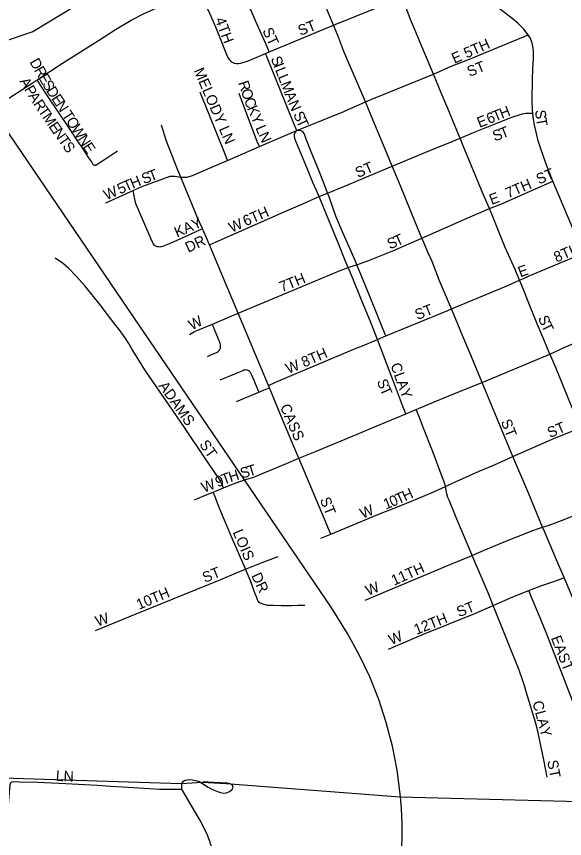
# Model space of a CAD drawing. Extents: x 0 to 34, y 0 to 22.
# Drawn here: x 30.158 to 30.651, y 14.628 to 15.366 of the extents above; entities that cross this region are included whole.
import ezdxf

# ---------------------------------------------------------------- set-up
doc = ezdxf.new("R2010")
doc.units = 0
for name, color, linetype in [('GM_X_City_Street', 7, 'Continuous'), ('GM_X_City_Street_Text', 7, 'Continuous'), ('GM_X_Corporation', 7, 'Continuous'), ('GM_X_Minor_River', 7, 'Continuous'), ('GM_X_State_Route', 7, 'Continuous'), ('GM_X_Township_Subdivision', 7, 'Continuous'), ('GM_X_Township_Subdivision_Text', 7, 'Continuous')]:
    doc.layers.add(name, color=color, linetype=linetype)

msp = doc.modelspace()

# ---------------------------------------------------------------- linework, layer by layer
at = {"layer": 'GM_X_City_Street'}
for points in [[(30.44327, 15.35778), (30.44035, 15.36499), (30.43212, 15.38492), (30.41886, 15.41649), (30.41429, 15.42742)], [(30.38556, 15.33389), (30.38354, 15.33843), (30.37364, 15.36119), (30.35762, 15.39828), (30.35533, 15.40356)], [(30.32272, 15.39), (30.32449, 15.38561), (30.32564, 15.38274), (30.32807, 15.37706), (30.33177, 15.36859), (30.33729, 15.35644), (30.34708, 15.33163), (30.34844, 15.32882), (30.34951, 15.32715), (30.35046, 15.32608), (30.35118, 15.32532), (30.35217, 15.32468), (30.35347, 15.32402), (30.35414, 15.32378), (30.35494, 15.32363), (30.35621, 15.3235), (30.35783, 15.32355), (30.35979, 15.32379), (30.36296, 15.32452), (30.36594, 15.32568), (30.38214, 15.33238)], [(30.61816, 15.34911), (30.61424, 15.35417), (30.61213, 15.35645), (30.60908, 15.35949), (30.60332, 15.36421), (30.59357, 15.37159), (30.5698, 15.39064)], [(30.44327, 15.35778), (30.50042, 15.38133), (30.50431, 15.38294)], [(30.53298, 15.31403), (30.52824, 15.32523), (30.52254, 15.33874), (30.52042, 15.3437), (30.51589, 15.3547), (30.51247, 15.36302), (30.5102, 15.36868), (30.50905, 15.37147), (30.50559, 15.3799), (30.50431, 15.38294)], [(30.17702, 15.30874), (30.19984, 15.32373), (30.23212, 15.34424), (30.24739, 15.35406), (30.26162, 15.36231), (30.27335, 15.36832), (30.29192, 15.37678)], [(30.38556, 15.33389), (30.4006, 15.34017), (30.44327, 15.35778)], [(30.47211, 15.28905), (30.46484, 15.30582), (30.45611, 15.32576), (30.45255, 15.33435), (30.447, 15.34855), (30.44327, 15.35778)], [(30.53298, 15.31403), (30.54819, 15.32065), (30.5639, 15.32686), (30.61395, 15.34738), (30.61816, 15.34911)], [(30.62214, 15.27888), (30.62186, 15.28172), (30.6216, 15.2909), (30.62194, 15.30942), (30.62228, 15.31867), (30.62279, 15.32791), (30.62296, 15.33419), (30.6227, 15.33736), (30.62208, 15.3405), (30.62108, 15.34354), (30.61974, 15.34643), (30.61816, 15.34911)], [(30.38214, 15.33238), (30.38556, 15.33389)], [(30.41019, 15.26328), (30.40817, 15.26814), (30.40136, 15.28521), (30.38362, 15.32883), (30.38214, 15.33238)], [(30.13629, 15.28267), (30.17253, 15.30579), (30.17702, 15.30874)], [(30.2494, 15.24479), (30.23857, 15.23768), (30.23007, 15.23214), (30.22965, 15.23192), (30.22933, 15.23187), (30.22898, 15.23186), (30.2286, 15.23197), (30.22824, 15.23219), (30.22767, 15.23266), (30.22746, 15.23297), (30.22581, 15.23543), (30.22353, 15.23877), (30.21756, 15.24817), (30.21433, 15.25286), (30.20568, 15.26591), (30.18626, 15.29435), (30.17952, 15.30486), (30.17702, 15.30874)], [(30.47211, 15.28905), (30.47759, 15.29146), (30.53298, 15.31403)], [(30.55689, 15.25657), (30.55641, 15.25771), (30.54583, 15.28314), (30.54001, 15.29701), (30.53298, 15.31403)], [(30.34806, 15.2365), (30.3459, 15.24198), (30.32358, 15.29783)], [(30.37664, 15.24885), (30.37483, 15.25357), (30.36266, 15.28528), (30.35855, 15.29668)], [(30.41019, 15.26328), (30.45242, 15.28035), (30.47211, 15.28905)], [(30.49591, 15.23135), (30.49102, 15.24296), (30.48038, 15.26877), (30.47211, 15.28905)], [(30.55689, 15.25657), (30.56902, 15.26143), (30.59304, 15.27098), (30.6043, 15.2755), (30.61006, 15.27751), (30.61305, 15.2783), (30.61595, 15.27877), (30.61881, 15.27901), (30.62214, 15.27888)], [(30.64034, 15.21782), (30.63697, 15.22615), (30.63384, 15.23414), (30.63143, 15.24092), (30.62962, 15.24599), (30.6272, 15.2542), (30.62566, 15.26068), (30.62344, 15.2696), (30.62245, 15.27563), (30.62214, 15.27888)], [(30.30615, 15.22134), (30.30347, 15.22774), (30.29335, 15.25378), (30.28871, 15.26823)], [(30.37664, 15.24885), (30.41019, 15.26328)], [(30.43023, 15.20408), (30.42461, 15.21663), (30.41977, 15.2285), (30.40939, 15.25364), (30.40863, 15.25604), (30.40825, 15.25845), (30.40832, 15.25996), (30.40882, 15.26148), (30.41019, 15.26328)], [(30.43794, 15.20724), (30.43599, 15.21218), (30.43025, 15.22682), (30.42332, 15.24413), (30.41884, 15.25549), (30.41781, 15.25821), (30.4168, 15.26059), (30.41597, 15.26174), (30.41471, 15.26275), (30.41331, 15.26325), (30.41019, 15.26328)], [(30.49591, 15.23135), (30.52966, 15.24528), (30.5497, 15.25359), (30.55689, 15.25657)], [(30.58334, 15.19328), (30.57781, 15.20616), (30.55983, 15.24956), (30.55689, 15.25657)], [(30.34806, 15.2365), (30.37664, 15.24885)], [(30.30615, 15.22134), (30.31185, 15.22134), (30.31656, 15.22281), (30.33443, 15.23061), (30.34806, 15.2365)], [(30.43794, 15.20724), (30.45244, 15.21317), (30.48672, 15.22756), (30.49591, 15.23135)], [(30.52257, 15.1668), (30.51837, 15.17697), (30.51361, 15.18842), (30.50665, 15.2057), (30.50189, 15.21719), (30.49591, 15.23135)], [(30.26333, 15.20939), (30.26845, 15.21189), (30.27435, 15.21439), (30.28834, 15.21939), (30.29651, 15.22229), (30.30072, 15.22238), (30.30615, 15.22134)], [(30.32569, 15.17513), (30.32551, 15.17552), (30.32303, 15.18098), (30.32064, 15.18647), (30.31613, 15.19744), (30.31167, 15.20816), (30.30615, 15.22134)], [(30.58334, 15.19328), (30.59348, 15.19731), (30.64034, 15.21782)], [(30.66776, 15.15339), (30.66601, 15.15747), (30.65677, 15.17901), (30.64034, 15.21782)], [(30.23863, 15.19836), (30.26333, 15.20939)], [(30.32569, 15.17513), (30.32359, 15.17416), (30.31115, 15.16845), (30.29983, 15.1633), (30.29405, 15.16097), (30.29116, 15.15976), (30.28954, 15.15914), (30.28831, 15.15885), (30.28738, 15.15876), (30.28642, 15.15882), (30.28528, 15.15895), (30.28429, 15.15927), (30.28347, 15.15955), (30.28279, 15.16), (30.28229, 15.16044), (30.28136, 15.16185), (30.28073, 15.16299), (30.27942, 15.16584), (30.26712, 15.19422), (30.26594, 15.19704), (30.26527, 15.20002), (30.26448, 15.2031), (30.26333, 15.20939)], [(30.43023, 15.20408), (30.43794, 15.20724)], [(30.46431, 15.14293), (30.46272, 15.14681), (30.45009, 15.17498), (30.44544, 15.1864), (30.43928, 15.20386), (30.43794, 15.20724)], [(30.33188, 15.16081), (30.33726, 15.16318), (30.399, 15.19044), (30.41579, 15.19765), (30.42896, 15.20352), (30.43023, 15.20408)], [(30.45642, 15.1404), (30.45384, 15.14659), (30.44816, 15.16101), (30.43282, 15.19827), (30.43023, 15.20408)], [(30.52257, 15.1668), (30.55848, 15.18246), (30.57077, 15.18799), (30.57574, 15.19003), (30.57902, 15.19155), (30.58334, 15.19328)], [(30.61032, 15.12891), (30.60629, 15.13851), (30.59744, 15.15833), (30.58611, 15.18684), (30.58334, 15.19328)], [(30.33188, 15.16081), (30.32918, 15.16713), (30.32569, 15.17513)], [(30.35763, 15.09937), (30.35671, 15.10154), (30.33887, 15.14442), (30.33281, 15.15864), (30.33188, 15.16081)], [(30.46431, 15.14293), (30.46892, 15.14446), (30.47416, 15.14631), (30.49666, 15.15547), (30.52257, 15.1668)], [(30.54919, 15.10323), (30.53858, 15.12834), (30.53183, 15.14577), (30.52799, 15.15424), (30.52425, 15.16272), (30.52257, 15.1668)], [(30.61032, 15.12891), (30.61341, 15.13028), (30.61911, 15.1328), (30.66776, 15.15339)], [(30.34441, 14.94265), (30.34259, 14.94696), (30.34043, 14.95087), (30.32776, 14.96957), (30.30872, 14.99775), (30.29295, 15.02063), (30.28416, 15.03328), (30.27378, 15.04863), (30.26887, 15.05646), (30.26247, 15.06696), (30.25942, 15.07227), (30.25613, 15.07741), (30.25066, 15.08478), (30.2469, 15.08965), (30.23367, 15.10676), (30.22011, 15.12365), (30.21194, 15.13293), (30.20545, 15.13955), (30.20074, 15.14354), (30.19315, 15.14886)], [(30.35763, 15.09937), (30.39772, 15.11613), (30.44927, 15.13783), (30.45642, 15.1404)], [(30.45642, 15.1404), (30.46193, 15.14213), (30.46431, 15.14293)], [(30.48266, 15.0759), (30.47683, 15.09093), (30.46823, 15.11209), (30.46071, 15.13049), (30.45642, 15.1404)], [(30.49021, 15.07899), (30.48791, 15.0847), (30.48363, 15.09533), (30.47544, 15.11533), (30.47089, 15.12681), (30.46431, 15.14293)], [(30.54919, 15.10323), (30.60048, 15.1245), (30.61032, 15.12891)], [(30.63742, 15.06251), (30.63228, 15.07584), (30.62631, 15.08994), (30.61914, 15.10697), (30.6123, 15.1242), (30.61032, 15.12891)], [(30.49021, 15.07899), (30.54586, 15.10185), (30.54919, 15.10323)], [(30.57663, 15.03734), (30.56647, 15.06173), (30.55925, 15.07935), (30.54919, 15.10323)], [(30.33445, 15.08969), (30.35763, 15.09937)], [(30.38485, 15.03464), (30.35763, 15.09937)], [(30.31386, 15.08018), (30.31842, 15.08299), (30.33445, 15.08969)], [(30.33016, 15.06061), (30.33303, 15.06202), (30.33594, 15.06321), (30.33881, 15.06453), (30.33957, 15.065), (30.34044, 15.06582), (30.341, 15.06668), (30.34138, 15.06731), (30.34172, 15.06814), (30.34186, 15.06893), (30.3419, 15.0699), (30.34176, 15.07092), (30.34143, 15.07215), (30.34112, 15.07305), (30.34, 15.07604), (30.33639, 15.08491), (30.33445, 15.08969)], [(30.63742, 15.06251), (30.65037, 15.0686), (30.68858, 15.08499), (30.69477, 15.08749)], [(30.48266, 15.0759), (30.49021, 15.07899)], [(30.38485, 15.03464), (30.39063, 15.03708), (30.46372, 15.06792), (30.46934, 15.07025), (30.48266, 15.0759)], [(30.50817, 15.00905), (30.50536, 15.0165), (30.49899, 15.03337), (30.48266, 15.0759)], [(30.34158, 15.03974), (30.35601, 15.04572), (30.36169, 15.04808), (30.3628, 15.04853), (30.36362, 15.0487), (30.3645, 15.04874), (30.36545, 15.04863), (30.36642, 15.04827), (30.36696, 15.04801), (30.36744, 15.04762), (30.36785, 15.04715), (30.36828, 15.04658), (30.36927, 15.04482), (30.3718, 15.03918), (30.37297, 15.03635), (30.37625, 15.02846)], [(30.38577, 15.03246), (30.38552, 15.03306), (30.38485, 15.03464)], [(30.60437, 14.97069), (30.60282, 14.97432), (30.57663, 15.03734)], [(30.3561, 15.02001), (30.37625, 15.02846)], [(30.37625, 15.02846), (30.38253, 15.0311), (30.38577, 15.03246)], [(30.41221, 14.96916), (30.40763, 14.97988), (30.39603, 15.00757), (30.38577, 15.03246)], [(30.54377, 14.94398), (30.54319, 14.94604), (30.5426, 14.94821), (30.54099, 14.9525), (30.53203, 14.97581), (30.52415, 14.99616), (30.51985, 15.00716), (30.51757, 15.013)], [(30.60437, 14.97069), (30.64173, 14.98723), (30.65912, 14.99401), (30.66524, 14.9964)], [(30.44077, 14.9012), (30.43876, 14.90594), (30.43756, 14.90878), (30.41221, 14.96916)], [(30.54377, 14.94398), (30.5508, 14.94718), (30.5741, 14.9575), (30.58784, 14.96334), (30.60437, 14.97069)], [(30.6311, 14.90735), (30.61858, 14.93738), (30.60437, 14.97069)], [(30.34441, 14.94265), (30.35264, 14.94611), (30.36327, 14.94984)], [(30.3184, 14.93198), (30.32123, 14.9331), (30.32691, 14.93539), (30.33532, 14.93884)], [(30.33532, 14.93884), (30.34441, 14.94265)], [(30.36427, 14.86961), (30.36381, 14.87072), (30.3516, 14.89877), (30.34716, 14.90937), (30.34357, 14.91774), (30.33964, 14.92748), (30.33639, 14.93603), (30.33532, 14.93884)], [(30.52401, 14.9353), (30.53385, 14.93942), (30.54377, 14.94398)], [(30.56783, 14.88208), (30.56744, 14.88297), (30.55412, 14.91454), (30.54705, 14.9315), (30.54606, 14.93387), (30.54497, 14.93733), (30.54438, 14.9405), (30.54377, 14.94398)], [(30.44077, 14.9012), (30.48458, 14.91923), (30.49914, 14.9251), (30.5168, 14.93234), (30.52401, 14.9353)], [(30.6311, 14.90735), (30.636, 14.9089), (30.64168, 14.91111), (30.65028, 14.9144), (30.68274, 14.92753), (30.69145, 14.93139)], [(30.56783, 14.88208), (30.57232, 14.88393), (30.59644, 14.8942), (30.62228, 14.90447), (30.62734, 14.90625), (30.63005, 14.90701), (30.6311, 14.90735)], [(30.65042, 14.86209), (30.64511, 14.87441), (30.63294, 14.90298), (30.6311, 14.90735)], [(30.43197, 14.8974), (30.44077, 14.9012)], [(30.36427, 14.86961), (30.37917, 14.87559), (30.39359, 14.8811)], [(30.47165, 14.84195), (30.54855, 14.87415), (30.56783, 14.88208)], [(30.58668, 14.83717), (30.58216, 14.84842), (30.56783, 14.88208)], [(30.22955, 14.81474), (30.26607, 14.82954), (30.34195, 14.86049), (30.35621, 14.86638), (30.36427, 14.86961)], [(30.3765, 14.83991), (30.3757, 14.84088), (30.37498, 14.84227), (30.37397, 14.84492), (30.37304, 14.84763), (30.36866, 14.85928), (30.36427, 14.86961)], [(30.61857, 14.8506), (30.62169, 14.85188), (30.63044, 14.85513), (30.63935, 14.85796), (30.64764, 14.86105), (30.65042, 14.86209)], [(30.65834, 14.84366), (30.65042, 14.86209)], [(30.58668, 14.83717), (30.60442, 14.84482), (30.61857, 14.8506)], [(30.66168, 14.73817), (30.66142, 14.74073), (30.661, 14.74272), (30.66062, 14.74412), (30.6596, 14.74701), (30.63424, 14.81277), (30.62739, 14.82973), (30.62144, 14.84381), (30.61857, 14.8506)], [(30.41756, 14.83715), (30.41139, 14.83699), (30.40545, 14.83692), (30.39623, 14.83679), (30.38944, 14.83699), (30.3841, 14.83725), (30.38084, 14.83796), (30.37835, 14.83877), (30.37734, 14.83928), (30.3765, 14.83991)], [(30.49275, 14.79792), (30.52421, 14.81129), (30.57021, 14.83004), (30.58668, 14.83717)], [(30.63507, 14.68296), (30.6323, 14.69869), (30.62864, 14.7158), (30.62687, 14.7244), (30.6248, 14.73244), (30.61658, 14.75882), (30.615, 14.76416), (30.61301, 14.77048), (30.60998, 14.77912), (30.58668, 14.83717)]]:
    msp.add_lwpolyline(points, dxfattribs=at)
at = {"layer": 'GM_X_Corporation'}
msp.add_lwpolyline([(29.75791, 15.20851), (29.79058, 15.21093), (29.86115, 15.29432), (29.91553, 15.1943), (29.9416, 15.13863), (29.94194, 15.10088), (29.94871, 15.04567), (29.96989, 14.94591), (30.07764, 14.93075), (30.06917, 14.68585), (30.09828, 14.68409), (30.30666, 14.67751), (30.32534, 14.67859), (30.34695, 14.67725), (30.50269, 14.66532), (30.73315, 14.65946), (30.803, 14.661), (30.81667, 14.62861)], dxfattribs=at)
at = {"layer": 'GM_X_Minor_River'}
msp.add_lwpolyline([(30.26003, 15.68689), (30.2593, 15.66897), (30.26815, 15.6398), (30.27368, 15.59278), (30.26354, 15.48955), (30.26512, 15.474), (30.27124, 15.46378), (30.26863, 15.45315), (30.25321, 15.42691), (30.21176, 15.37513), (30.1732, 15.35183), (30.124, 15.3353), (30.06759, 15.3214), (30.02369, 15.30528), (29.99036, 15.30096), (29.94494, 15.28748), (29.91698, 15.26877), (29.86752, 15.22531), (29.84824, 15.21385), (29.81119, 15.19358), (29.77572, 15.16004)], dxfattribs=at)
at = {"layer": 'GM_X_State_Route'}
for points in [[(30.36327, 14.94984), (30.35876, 14.95655), (30.2641, 15.09534), (30.13629, 15.28267), (30.11506, 15.3138), (30.09374, 15.34496), (30.0929, 15.3462)], [(30.36327, 14.94984), (30.37059, 14.95202), (30.37317, 14.95293), (30.37648, 14.95426), (30.40118, 14.96455), (30.41221, 14.96916), (30.42703, 14.97536), (30.46441, 14.99085), (30.48165, 14.99794), (30.49885, 15.00514), (30.50817, 15.00905), (30.51757, 15.013), (30.53319, 15.01955), (30.5579, 15.02959), (30.57663, 15.03734), (30.62109, 15.05576), (30.63742, 15.06251)], [(30.63742, 15.06251), (30.64285, 15.04994), (30.6488, 15.03548), (30.65465, 15.02134), (30.65703, 15.01572), (30.65943, 15.01015), (30.66299, 15.00186), (30.66524, 14.9964), (30.68036, 14.95966), (30.68245, 14.95396), (30.68463, 14.94828), (30.68697, 14.94263), (30.69145, 14.93139)], [(30.50346, 14.66582), (30.50045, 14.68943), (30.49621, 14.71085), (30.49067, 14.73197), (30.48386, 14.75271), (30.47579, 14.77301), (30.4664, 14.79272), (30.45591, 14.81186), (30.44106, 14.83566), (30.36327, 14.94984)], [(30.41106, 14.2976), (30.44516, 14.37223), (30.45625, 14.3969), (30.46221, 14.4113), (30.46824, 14.42901), (30.47342, 14.44835), (30.47623, 14.45958), (30.47826, 14.46865), (30.48359, 14.49251), (30.49722, 14.55635), (30.50129, 14.58093), (30.50339, 14.59947), (30.50475, 14.62122), (30.50481, 14.62824), (30.50493, 14.63438), (30.50484, 14.64237), (30.50458, 14.64816), (30.50423, 14.65453), (30.50349, 14.66561), (30.50346, 14.66582)]]:
    msp.add_lwpolyline(points, dxfattribs=at)
at = {"layer": 'GM_X_Township_Subdivision'}
for points in [[(30.3069, 14.67216), (30.30708, 14.6761), (30.30746, 14.67781), (30.30861, 14.67948), (30.31, 14.68033), (30.31328, 14.68093), (30.31653, 14.68073), (30.31966, 14.68015), (30.32269, 14.67905), (30.32551, 14.67752), (30.33075, 14.67416), (30.3334, 14.67269), (30.33614, 14.67137), (30.33897, 14.67019), (30.34182, 14.66915), (30.34454, 14.66866), (30.34713, 14.66904), (30.34974, 14.67016), (30.35204, 14.67183), (30.35323, 14.67387), (30.35267, 14.67579), (30.35059, 14.67702), (30.34775, 14.67754), (30.34164, 14.67796), (30.33545, 14.67825), (30.32613, 14.67888)], [(30.14839, 14.62282), (30.14892, 14.62905), (30.15298, 14.67664), (30.15306, 14.67709), (30.15313, 14.67758), (30.15354, 14.67838), (30.15439, 14.67884), (30.15549, 14.67904), (30.16102, 14.67896), (30.17783, 14.6785), (30.20284, 14.67738), (30.23094, 14.67575), (30.24335, 14.67497), (30.25886, 14.67407), (30.2776, 14.67289), (30.28699, 14.67239), (30.29637, 14.6722), (30.3069, 14.67216)], [(30.34328, 14.57631), (30.3398, 14.59544), (30.33791, 14.60451), (30.3348, 14.6165), (30.33211, 14.62535), (30.32999, 14.63109), (30.32751, 14.63663), (30.32318, 14.64467), (30.31243, 14.66307), (30.3069, 14.67216)]]:
    msp.add_lwpolyline(points, dxfattribs=at)

# ---------------------------------------------------------------- texts
at = {"layer": 'GM_X_City_Street_Text'}
for s, rotation, p in [('4TH', 290.55505, (30.33672, 15.36294)), ('ST', 21.80392, (30.41355, 15.34814)), ('ST', 295.02966, (30.37916, 15.35307)), ('E 5TH', 23.80864, (30.55187, 15.32313)), ('S', 291.42594, (30.38671, 15.32796)), ('D', 299.57682, (30.16994, 15.32485)), ('I', 291.46546, (30.38914, 15.32175)), ('ST', 21.80141, (30.56544, 15.31134)), ('R', 299.61345, (30.17405, 15.3176)), ('MELODY LN', 293.38335, (30.31752, 15.31719)), ('L', 291.42594, (30.39067, 15.31788)), ('A', 300.9975, (30.16087, 15.30748)), ('E', 299.80675, (30.17777, 15.31104)), ('S', 301.30715, (30.18123, 15.30503)), ('R', 288.51176, (30.35757, 15.30621)), ('L', 291.43089, (30.3931, 15.31167)), ('M', 291.4429, (30.39554, 15.30547)), ('P', 301.29035, (30.16519, 15.30029)), ('D', 302.82743, (30.18484, 15.2991)), ('O', 288.48334, (30.35996, 15.2991)), ('A', 302.20933, (30.16874, 15.29445)), ('E', 303.75379, (30.18945, 15.29196)), ('A', 291.4728, (30.3992, 15.29615)), ('R', 303.10373, (30.17326, 15.28726)), ('T', 304.10148, (30.17746, 15.28083)), ('N', 303.05961, (30.19314, 15.28644)), ('C', 290.26259, (30.36271, 15.29089)), ('K', 293.01017, (30.36548, 15.2834)), ('N', 293.44813, (30.40239, 15.28807)), ('H', 21.83794, (30.59451, 15.2737)), ('M', 304.66343, (30.18126, 15.27523)), ('T', 303.05365, (30.19905, 15.27736)), ('Y', 293.17608, (30.36875, 15.2757)), ('S', 294.58175, (30.40682, 15.27796)), ('6', 21.85359, (30.58291, 15.26905)), ('T', 21.83184, (30.58832, 15.27122)), ('S', 275.1425, (30.62433, 15.28156)), ('E', 304.76278, (30.18695, 15.26699)), ('O', 303.05961, (30.20268, 15.27177)), ('T', 294.62131, (30.4096, 15.2719)), ('E', 21.83184, (30.57439, 15.26564)), ('T', 279.88365, (30.62504, 15.27407)), ('N', 304.79555, (30.19076, 15.2615)), ('W', 303.03727, (30.20723, 15.26479)), ('L', 293.19142, (30.37302, 15.26574)), ('S', 18.57317, (30.58797, 15.25355)), ('T', 21.99313, (30.59487, 15.25589)), ('T', 305.09338, (30.19554, 15.25461)), ('N', 303.06808, (30.21314, 15.2557)), ('N', 293.19649, (30.37565, 15.25961)), ('S', 305.6557, (30.19944, 15.24908)), ('E', 303.0706, (30.21768, 15.24871)), ('ST', 23.20047, (30.46518, 15.22062)), ('T', 20.54325, (30.27911, 15.21741)), ('ST', 23.20047, (30.62768, 15.21478)), ('T', 23.7655, (30.25687, 15.20834)), ('H', 22.56439, (30.26292, 15.211)), ('S', 20.62958, (30.27288, 15.21506)), ('7TH', 23.49613, (30.60017, 15.20228)), ('W', 23.77473, (30.23933, 15.20061)), ('5', 23.76786, (30.25153, 15.20599)), ('E', 20.53808, (30.58526, 15.19648)), ('6TH', 23.49266, (30.36434, 15.17728)), ('KAY', 23.20047, (30.30273, 15.16718)), ('W', 24.42898, (30.35181, 15.17144)), ('DR', 25.19679, (30.31282, 15.15351)), ('S', 22.72496, (30.49383, 15.15657)), ('T', 24.59778, (30.50028, 15.15928)), ('8TH', 22.99194, (30.64351, 15.14478)), ('E', 20.54706, (30.61109, 15.13148)), ('7TH', 22.10926, (30.39688, 15.11813)), ('ST', 21.80392, (30.51855, 15.09314)), ('W', 26.55048, (30.31592, 15.08391)), ('S', 291.39054, (30.62678, 15.09526)), ('T', 295.94398, (30.62955, 15.0883)), ('8TH', 23.49266, (30.41684, 15.05062)), ('W', 22.62245, (30.4027, 15.04479)), ('CLAY', 289.85626, (30.49422, 15.05292)), ('ADAMS', 305.27511, (30.28567, 15.03418)), ('S', 288.72009, (30.48212, 15.03855)), ('T', 294.42348, (30.48464, 15.03127)), ('CASS', 293.62831, (30.39501, 15.01553)), ('ST', 291.78635, (30.59338, 15.00215)), ('ST', 23.20047, (30.63768, 14.98729)), ('ST', 304.69079, (30.32235, 14.98166)), ('S', 16.68092, (30.36101, 14.95088)), ('T', 16.68486, (30.3674, 14.9528)), ('9', 21.75354, (30.33928, 14.94308)), ('T', 21.1925, (30.34467, 14.94523)), ('H', 18.02027, (30.35075, 14.94759)), ('W', 21.75457, (30.32688, 14.93814)), ('T', 24.11798, (30.50137, 14.92775)), ('H', 24.24683, (30.50748, 14.93049)), ('ST', 291.7989, (30.43087, 14.93215)), ('1', 21.92319, (30.49023, 14.92314)), ('0', 23.00255, (30.49581, 14.92539)), ('W', 22.62245, (30.46936, 14.91479)), ('LOIS', 293.20048, (30.35252, 14.90302)), ('11TH', 24.14402, (30.49765, 14.85477)), ('ST', 21.80392, (30.32772, 14.8573)), ('DR', 295.1968, (30.36916, 14.86391)), ('W', 22.62245, (30.47436, 14.84562)), ('10TH', 22.83802, (30.26853, 14.83312)), ('ST', 21.7989, (30.55605, 14.82647)), ('W', 18.42402, (30.23115, 14.81817)), ('12TH', 21.80392, (30.51772, 14.81064)), ('W', 22.60693, (30.4952, 14.80146)), ('EAST', 291.50162, (30.63837, 14.80797)), ('CLAY', 285.12878, (30.62177, 14.75026)), ('ST', 280.61472, (30.63513, 14.69764))]:
    msp.add_text(s, height=0.00947, rotation=rotation, dxfattribs=at).set_placement(p)
at = {"layer": 'GM_X_Township_Subdivision_Text'}
for s, rotation, p in [('L', 355.4337, (30.19357, 14.67992)), ('N', 358.19335, (30.20071, 14.67936))]:
    msp.add_text(s, height=0.00947, rotation=rotation, dxfattribs=at).set_placement(p)

doc.saveas('drawing.dxf')
